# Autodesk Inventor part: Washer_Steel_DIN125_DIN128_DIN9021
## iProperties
Author: Jørgen Albe Bjørnes
Shininess: 25.0
PropertySet Name: _Private Model Information
Created: 2001-01
Part Number: Washer_Steel_DIN125_DIN128_DIN9021
Material: Steel
Description: Washer M8
Vendor: DIN 125
Document SubType Name: Modeling
Designer: Jørgen Albe Bjørnes
Control State: 0
Master: False
Checked Out: False
PropertySet Name: Design Tracking Control
Density: 0.0
Volumn: 0.0
Area: 0.0
PropertySet Name: Model Information
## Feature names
1. Extrusion1
2. Extrusion2
